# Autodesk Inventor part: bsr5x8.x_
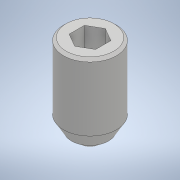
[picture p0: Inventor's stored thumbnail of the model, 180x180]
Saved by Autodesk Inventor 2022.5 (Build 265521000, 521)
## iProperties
Created: 2020-01
Part Number: bsr5x8.x_
Material: 一般
Document SubType Name: Modeling
Designer: ImaoCorp
Density: 1 g/cm^3
Appearance: 既定
Sending System: SOLIDWORKS 2018-2018316
MC: AMD64
MC_MODEL: Intel64 Family 6 Model 60 Stepping 3, GenuineIntel
OS: Windows_NT
FRU: Parasolid Version 30.0, build 310,  6- 8-2018
FORMAT: text
GUISE: transmit
KEY: bsr5x8
FILE: bsr5x8.x_t
DATE: Thu Jan 23 16:47:16 2020
Author: ImaoCorp
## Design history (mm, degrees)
feature "Base1"
node "ソリッド1"
